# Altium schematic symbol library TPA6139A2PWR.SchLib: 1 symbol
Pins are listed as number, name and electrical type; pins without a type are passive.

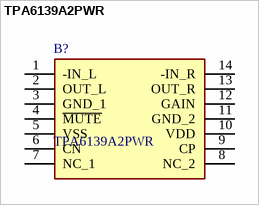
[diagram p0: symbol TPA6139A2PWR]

## TPA6139A2PWR
designator B?
DirectPath 25mW Headphone Amplifier; Manufacturer_Name: Texas Instruments; Geometry.Height: 1.2mm
footprint SOP65P640X120-14N
pins: 1 -IN_L, 2 OUT_L, 3 GND_1, 4 ~{MUTE}, 5 VSS, 6 CN, 7 NC_1, 8 NC_2, 9 CP, 10 VDD, 11 GND_2, 12 GAIN, 13 OUT_R, 14 -IN_R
